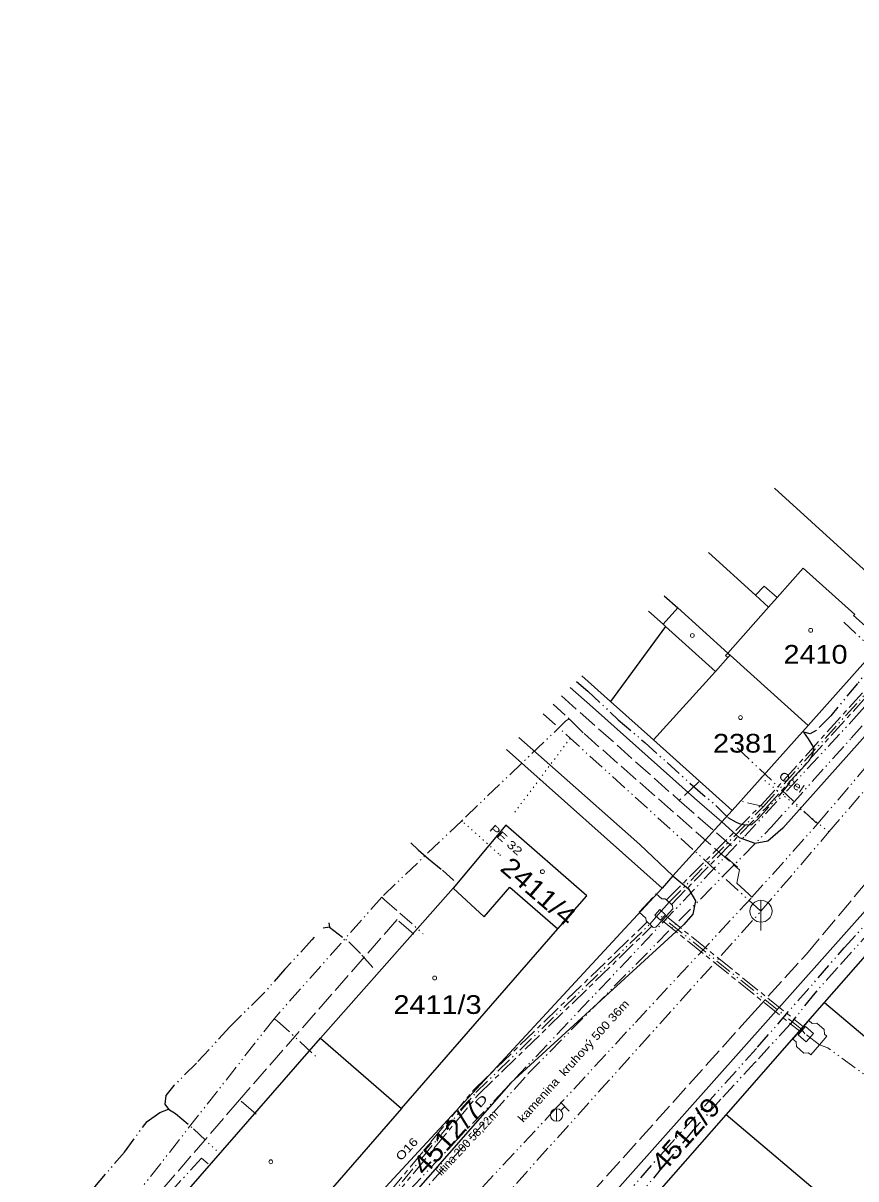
# Model space of a CAD drawing. Extents: x -683947 to -683762, y -1065756 to -1065543.
# Drawn here: x -683919.6 to -683844, y -1065654 to -1065549.1 of the extents above; entities that cross this region are included whole.
import ezdxf

# ---------------------------------------------------------------- set-up
doc = ezdxf.new("R2010")
doc.units = 0
doc.header["$LTSCALE"] = 0.3
for name, pattern in [('DASH_DOUBLE_DOT', [9.2, 5, -1.2, 0.3, -1.2, 0.3, -1.2]), ('DOTTED', [1.5, 0.3, -1.2]), ('LONG_DASH_SHORT_DASH', [9.9, 6, -1.2, 1.5, -1.2]), ('LONG_DASHED', [7.5, 6, -1.5])]:
    doc.linetypes.add(name, pattern=pattern)
for name, color, linetype, lineweight in [('1', 7, 'Continuous', 25), ('10', 7, 'Continuous', 13), ('26', 7, 'LONG_DASH_SHORT_DASH', 13), ('30', 7, 'LONG_DASHED', 13), ('31', 7, 'DASH_DOUBLE_DOT', 13), ('35', 7, 'LONG_DASHED', 13), ('36', 7, 'DASH_DOUBLE_DOT', 25), ('4', 7, 'Continuous', 13), ('41', 7, 'DASH_DOUBLE_DOT', 13), ('46', 7, 'DASH_DOUBLE_DOT', 13), ('5', 7, 'Continuous', 13), ('50', 7, 'LONG_DASHED', 13), ('51', 7, 'DOTTED', 13)]:
    doc.layers.add(name, color=color, linetype=linetype, lineweight=lineweight)
for name, color, linetype in [('15', 7, 'Continuous'), ('16', 7, 'Continuous'), ('19', 7, 'Continuous'), ('2', 7, 'Continuous')]:
    doc.layers.add(name, color=color, linetype=linetype)

msp = doc.modelspace()

# ---------------------------------------------------------------- linework, layer by layer
at = {"layer": '1'}
for p, q in [((-683799.39, -1065564.75), (-683850.61, -1065622.17)), ((-683844.35, -1065631.04), (-683799.69, -1065580.85)), ((-683839.12, -1065602.44), (-683851.364, -1065591.312)), ((-683861.375, -1065601.074), (-683860.14, -1065602.18)), ((-683862.798, -1065602.462), (-683861.47, -1065603.66)), ((-683860.14, -1065602.18), (-683855.6, -1065606.27)), ((-683861.25, -1065603.86), (-683866.24, -1065610.67)), ((-683861.47, -1065603.66), (-683861.25, -1065603.86)), ((-683841.53, -1065605.24), (-683848.31, -1065612.84)), ((-683855.6, -1065606.27), (-683855.38, -1065606.47)), ((-683855.38, -1065606.47), (-683848.31, -1065612.84)), ((-683868.839, -1065608.352), (-683866.24, -1065610.67)), ((-683866.24, -1065610.67), (-683862.34, -1065614.14)), ((-683848.31, -1065612.84), (-683855.19, -1065620.55)), ((-683862.34, -1065614.14), (-683855.19, -1065620.55)), ((-683861.55, -1065627.6), (-683875.681, -1065615.023)), ((-683855.19, -1065620.55), (-683856.15, -1065621.6)), ((-683875.75, -1065621.9), (-683880.52, -1065627.61)), ((-683868.4, -1065628.3), (-683875.75, -1065621.9)), ((-683856.15, -1065621.6), (-683860.6, -1065626.48)), ((-683854.54, -1065623.06), (-683856.15, -1065621.6)), ((-683860.6, -1065626.48), (-683861.55, -1065627.6)), ((-683860.6, -1065626.48), (-683859.17, -1065627.69)), ((-683861.55, -1065627.6), (-683902.49, -1065671.82)), ((-683880.52, -1065627.61), (-683892.56, -1065641.22)), ((-683880.52, -1065627.61), (-683877.73, -1065630.22)), ((-683877.73, -1065630.22), (-683875.38, -1065627.52)), ((-683875.38, -1065627.52), (-683871.02, -1065631.31)), ((-683859.17, -1065627.69), (-683858.54, -1065628.75)), ((-683871.02, -1065631.31), (-683868.4, -1065628.3)), ((-683858.54, -1065628.75), (-683858.77, -1065629.96)), ((-683858.77, -1065629.96), (-683859.58, -1065630.9)), ((-683885.21, -1065647.62), (-683871.02, -1065631.31)), ((-683867.65, -1065657.22), (-683844.35, -1065631.04)), ((-683846.81, -1065638), (-683842.21, -1065632.76)), ((-683855.75, -1065648.18), (-683846.81, -1065638)), ((-683846.81, -1065638), (-683835.924, -1065647.198)), ((-683909.31, -1065660.38), (-683892.56, -1065641.22)), ((-683863.13, -1065656.59), (-683855.75, -1065648.18)), ((-683845.419, -1065656.92), (-683855.75, -1065648.18))]:
    msp.add_line(p, q, dxfattribs=at)
for points in [[(-683850.61, -1065622.17), (-683851.95, -1065623.34), (-683853.1, -1065623.57), (-683854.54, -1065623.06)], [(-683859.58, -1065630.9), (-683875.3, -1065645.28), (-683888.43, -1065660.25), (-683897.91, -1065674.98), (-683898.51, -1065675.59)], [(-683892.56, -1065641.22), (-683885.21, -1065647.62), (-683901.98, -1065666.88)]]:
    msp.add_lwpolyline(points, dxfattribs=at)
at = {"layer": '10'}
for p, q in [((-683852.585, -1065628.702), (-683852.585, -1065631.45)), ((-683870.777, -1065647.051), (-683869.986, -1065647.842)), ((-683871.138, -1065648.762), (-683871.137, -1065647.644)), ((-683870.743, -1065647.808), (-683870.381, -1065647.446))]:
    msp.add_line(p, q, dxfattribs=at)
for centre, radius in [((-683852.585, -1065629.704), 1), ((-683871.138, -1065648.203), 0.559)]:
    msp.add_circle(centre, radius, dxfattribs=at)
at = {"layer": '26'}
for p, q in [((-683861.2, -1065630.15), (-683848.73, -1065640.2)), ((-683861.56, -1065630.54), (-683849.07, -1065640.6))]:
    msp.add_line(p, q, dxfattribs=at)
for points in [[(-683861.16, -1065628.68), (-683852.54, -1065620.04), (-683840.5, -1065606.72), (-683835.07, -1065600.93)], [(-683860.72, -1065629.09), (-683852.18, -1065620.38), (-683840.14, -1065607.06), (-683834.72, -1065601.23)], [(-683903.43, -1065669.5), (-683897.38, -1065669.58), (-683878.26, -1065646.37), (-683862.48, -1065631.07)], [(-683903.42, -1065669.04), (-683897.66, -1065668.98), (-683878.7, -1065645.97), (-683862.91, -1065630.67)]]:
    msp.add_lwpolyline(points, dxfattribs=at)
for points in [[(-683863.63, -1065629.78), (-683862.1, -1065628.12), (-683861.58, -1065628.59), (-683861.27, -1065628.58), (-683861.16, -1065628.68), (-683860.72, -1065629.09), (-683860.61, -1065629.19), (-683860.6, -1065629.5), (-683861.2, -1065630.15), (-683861.56, -1065630.54), (-683862.13, -1065631.16), (-683862.37, -1065631.17), (-683862.48, -1065631.07), (-683862.91, -1065630.67), (-683863.02, -1065630.57), (-683863.03, -1065630.33)], [(-683862.23, -1065630.06), (-683861.76, -1065629.55), (-683861.24, -1065630.02), (-683861.72, -1065630.53)], [(-683849.7, -1065641.32), (-683849.07, -1065640.6), (-683848.73, -1065640.2), (-683848.24, -1065639.64), (-683847.95, -1065639.9), (-683847.53, -1065639.86), (-683846.85, -1065640.45), (-683846.81, -1065640.88), (-683846.6, -1065641.06), (-683847.26, -1065641.82), (-683847.66, -1065642.29), (-683848.05, -1065642.74), (-683848.27, -1065642.56), (-683848.69, -1065642.59), (-683849.37, -1065642), (-683849.4, -1065641.57)], [(-683849.2, -1065640.93), (-683848.55, -1065640.17), (-683847.82, -1065640.8), (-683848.47, -1065641.56)]]:
    msp.add_lwpolyline(points, close=True, dxfattribs=at)
at = {"layer": '30', "linetype": 'DASH_DOUBLE_DOT'}
msp.add_line((-683852.36, -1065620.21), (-683854.49, -1065619.69), dxfattribs=at)
at = {"layer": '31'}
for p, q in [((-683852.36, -1065620.21), (-683840.32, -1065606.89)), ((-683854.06, -1065622.89), (-683844.16, -1065612.25))]:
    msp.add_line(p, q, dxfattribs=at)
for points in [[(-683844.16, -1065612.25), (-683839.52, -1065607), (-683832.27, -1065598.52), (-683799.27, -1065561.98), (-683793.42, -1065555.08), (-683787.795, -1065549.096)], [(-683851.65, -1065622.08), (-683844.4, -1065614), (-683839.42, -1065608.5)], [(-683861.88, -1065629.98), (-683860.92, -1065628.89), (-683852.36, -1065620.21)], [(-683914.84, -1065689.19), (-683909.62, -1065682.86), (-683896.8, -1065669.54), (-683888.32, -1065659.06), (-683854.06, -1065622.89)], [(-683906.37, -1065683.43), (-683899.08, -1065675.36), (-683887.96, -1065660.41), (-683873.71, -1065644.44), (-683851.65, -1065622.08)], [(-683904.31, -1065669.83), (-683903.47, -1065669.28), (-683897.52, -1065669.28), (-683878.48, -1065646.17), (-683862.67, -1065630.88), (-683861.88, -1065629.98)], [(-683847.26, -1065641.82), (-683848.59, -1065640.84), (-683848.91, -1065640.4), (-683861.88, -1065629.98)], [(-683837.249, -1065648.554), (-683837.47, -1065648.39), (-683839.53, -1065647.2), (-683846.53, -1065642.1), (-683847.26, -1065641.82)], [(-683902.77, -1065652.64), (-683903.37, -1065652.11), (-683910.28, -1065659.68), (-683910.65, -1065661.62), (-683904.7, -1065669)]]:
    msp.add_lwpolyline(points, dxfattribs=at)
at = {"layer": '35'}
msp.add_line((-683853.691, -1065628.152), (-683853.405, -1065628.437), dxfattribs=at)
for points in [[(-683896.24, -1065687.55), (-683894.71, -1065685.72), (-683893.48, -1065684.13), (-683891.61, -1065681.955), (-683887.89, -1065677.63), (-683886.16, -1065675.53), (-683853.44, -1065639.1), (-683848.45, -1065633.59), (-683843.114, -1065627.22), (-683843.08, -1065627.18), (-683831.4, -1065614.21), (-683820.06, -1065601.41), (-683812.91, -1065593.55), (-683807.75, -1065587.62), (-683793.84, -1065572.21), (-683791.969, -1065570.179), (-683790.708, -1065568.809), (-683790.074, -1065568.129)], [(-683870.696, -1065610.163), (-683860.01, -1065619.65), (-683855.11, -1065623.91)], [(-683870.005, -1065612.249), (-683868.647, -1065613.585), (-683854.756, -1065625.769), (-683854.545, -1065625.954), (-683854.783, -1065627.15), (-683853.691, -1065628.152)], [(-683899.923, -1065646.829), (-683919.379, -1065669.399), (-683919.57, -1065669.63)]]:
    msp.add_lwpolyline(points, dxfattribs=at)
at = {"layer": '36', "lineweight": 13}
for p, q in [((-683871.452, -1065610.9), (-683870.005, -1065612.249)), ((-683870.287, -1065612.435), (-683870.005, -1065612.249)), ((-683854.71, -1065625.713), (-683856.125, -1065624.479))]:
    msp.add_line(p, q, dxfattribs=at)
for points in [[(-683853.405, -1065628.437), (-683847.424, -1065621.75), (-683837.692, -1065610.319), (-683826.563, -1065598.101), (-683821.765, -1065592.734), (-683810.241, -1065579.722), (-683798.152, -1065565.762), (-683797.335, -1065564.872), (-683796.84, -1065564.29)], [(-683870.287, -1065612.435), (-683879.753, -1065621.49), (-683887.014, -1065628.435), (-683896.789, -1065639.476), (-683918.858, -1065667.62)], [(-683893.079, -1065671.05), (-683871.468, -1065647.886), (-683863.976, -1065639.798), (-683853.405, -1065628.437)]]:
    msp.add_lwpolyline(points, dxfattribs=at)
at = {"layer": '36'}
for points in [[(-683842.215, -1065607.115), (-683843.83, -1065609.03), (-683846.24, -1065611.96), (-683847.58, -1065613.3), (-683848.12, -1065613.6), (-683848.69, -1065613.45)], [(-683869.343, -1065608.844), (-683868.3, -1065609.72), (-683865.54, -1065612.33), (-683863.14, -1065614.38), (-683861.11, -1065616.21), (-683858.79, -1065618.31), (-683856.69, -1065620.11), (-683855.58, -1065621.21), (-683854.85, -1065621.62), (-683854.57, -1065621.75), (-683854.07, -1065621.88), (-683853.43, -1065621.83), (-683852.88, -1065621.35), (-683850.88, -1065619.18), (-683849.15, -1065617.08), (-683848.11, -1065615.9), (-683847.84, -1065615.36), (-683847.8, -1065614.86), (-683848.27, -1065614.07), (-683848.69, -1065613.45)], [(-683884.364, -1065623.49), (-683883.71, -1065624.12), (-683882.78, -1065624.95), (-683881.51, -1065625.99), (-683880.48, -1065626.93)], [(-683891.81, -1065630.751), (-683891.76, -1065631.15), (-683892.33, -1065631.258)], [(-683891.76, -1065631.15), (-683890.01, -1065632.48), (-683888.81, -1065633.69), (-683887.63, -1065635.07)], [(-683842.53, -1065631.36), (-683845.66, -1065634.87), (-683847.69, -1065637.13), (-683849.92, -1065639.94), (-683853.13, -1065643.44), (-683856.24, -1065646.78), (-683858.76, -1065649.61), (-683861.4, -1065652.77), (-683863.72, -1065655.58)], [(-683893.15, -1065632.058), (-683893.35, -1065632.31), (-683895.8, -1065634.96), (-683897.77, -1065637.2), (-683900.81, -1065640.2), (-683903.84, -1065643.51), (-683905.89, -1065645.54), (-683906.62, -1065646.43), (-683906.71, -1065647.21), (-683906.37, -1065647.66)], [(-683918.74, -1065659.99), (-683918.38, -1065659.72), (-683916.63, -1065658.62), (-683914.98, -1065657.12), (-683913.07, -1065654.72), (-683910.37, -1065651.57), (-683908.32, -1065648.79), (-683907.17, -1065647.97), (-683906.37, -1065647.66)], [(-683906.37, -1065647.66), (-683905.73, -1065648.06), (-683904.1, -1065649.47), (-683902.01, -1065651.44)]]:
    msp.add_lwpolyline(points, dxfattribs=at)
at = {"layer": '4'}
for p, q in [((-683853.09, -1065601.01), (-683857.361, -1065597.16)), ((-683848.77, -1065598.58), (-683851.11, -1065601.23)), ((-683844.07, -1065602.76), (-683848.77, -1065598.58)), ((-683852.3, -1065600.21), (-683853.09, -1065601.01)), ((-683851.11, -1065601.23), (-683852.3, -1065600.21)), ((-683861.47, -1065603.66), (-683860.14, -1065602.18)), ((-683855.6, -1065606.27), (-683851.89, -1065602.1)), ((-683861.25, -1065603.86), (-683856.72, -1065607.95)), ((-683855.58, -1065606.69), (-683856.72, -1065607.95)), ((-683856.72, -1065607.95), (-683862.34, -1065614.14)), ((-683869.905, -1065609.392), (-683867.87, -1065611.2)), ((-683867.87, -1065611.2), (-683858.62, -1065619.44)), ((-683871.24, -1065616.88), (-683874.581, -1065613.951)), ((-683858.62, -1065619.44), (-683856.15, -1065621.6))]:
    msp.add_line(p, q, dxfattribs=at)
for points in [[(-683853.09, -1065601.01), (-683851.89, -1065602.1), (-683851.11, -1065601.23)], [(-683841.53, -1065605.24), (-683844.18, -1065602.88), (-683844.07, -1065602.76)], [(-683855.38, -1065606.47), (-683855.58, -1065606.69), (-683855.8, -1065606.49), (-683855.6, -1065606.27)], [(-683860.6, -1065626.48), (-683863.57, -1065623.65), (-683871.24, -1065616.88)]]:
    msp.add_lwpolyline(points, dxfattribs=at)
at = {"layer": '41', "lineweight": 25}
msp.add_lwpolyline([(-683907.26, -1065705.67), (-683893.37, -1065687.98), (-683887.71, -1065681.96), (-683876.81, -1065669.67), (-683869.01, -1065660.17), (-683861.43, -1065651.54), (-683852.89, -1065642.04), (-683845.02, -1065633.03), (-683836.31, -1065623.45), (-683820.34, -1065605.7), (-683789.54, -1065571.05), (-683781.76, -1065562.31), (-683777.124, -1065557.504)], dxfattribs=at)
at = {"layer": '46'}
for p, q in [((-683872.355, -1065611.781), (-683869.903, -1065614.004)), ((-683852.585, -1065629.704), (-683869.903, -1065614.004)), ((-683876.643, -1065656.48), (-683852.585, -1065629.704))]:
    msp.add_line(p, q, dxfattribs=at)
msp.add_lwpolyline([(-683852.585, -1065629.704), (-683846.423, -1065622.515), (-683835.949, -1065610.295), (-683830.355, -1065603.769), (-683826.197, -1065598.918)], dxfattribs=at)
at = {"layer": '5'}
for centre in [(-683848.077, -1065604.209), (-683858.817, -1065604.679), (-683854.447, -1065612.129), (-683872.427, -1065626.119), (-683882.207, -1065635.769), (-683897.077, -1065652.449)]:
    msp.add_circle(centre, 0.175, dxfattribs=at)
at = {"layer": '50'}
for p, q in [((-683858.22, -1065617.95), (-683860.01, -1065619.65)), ((-683898.413, -1065648.141), (-683899.923, -1065646.829))]:
    msp.add_line(p, q, dxfattribs=at)
msp.add_lwpolyline([(-683884.103, -1065631.779), (-683885.613, -1065630.467), (-683899.923, -1065646.829)], dxfattribs=at)
at = {"layer": '51'}
for p, q in [((-683869.903, -1065614.004), (-683875.123, -1065620.97)), ((-683846.423, -1065622.515), (-683852.885, -1065617.332))]:
    msp.add_line(p, q, dxfattribs=at)
at = {"layer": '51', "linetype": 'DASH_DOUBLE_DOT'}
for points in [[(-683837.692, -1065610.319), (-683837.85, -1065610.18), (-683845.274, -1065603.286)], [(-683847.424, -1065621.75), (-683847.6, -1065621.64), (-683854.966, -1065614.685)], [(-683887.014, -1065628.435), (-683886.775, -1065628.66), (-683885.383, -1065629.871), (-683883.259, -1065631.756)], [(-683896.789, -1065639.476), (-683896.496, -1065639.644), (-683892.926, -1065642.949)]]:
    msp.add_lwpolyline(points, dxfattribs=at)
at = {"layer": '51'}
msp.add_lwpolyline([(-683879.753, -1065621.49), (-683879.55, -1065621.672), (-683876.308, -1065624.578), (-683876.15, -1065624.719)], dxfattribs=at)

# ---------------------------------------------------------------- texts
at = {"layer": '15'}
for s, width, p in [('kamenina  kruhový 500 36m', 1.15, (-683874.172, -1065648.942)), ('D', 1.6, (-683878.098, -1065647.626))]:
    msp.add_text(s, height=0.75, rotation=48.06, dxfattribs=dict(at, width=width)).set_placement(p)
at = {"layer": '16'}
msp.add_text('litina 200 58,22m', height=0.75, rotation=46.99, dxfattribs=at).set_placement((-683881.603, -1065653.764))
at = {"layer": '16', "width": 1.25}
msp.add_text('O16', height=0.75, rotation=46.99, dxfattribs=at).set_placement((-683885.269, -1065652.418))
at = {"layer": '19'}
for s, rotation, width, p in [('Ocel ', 325.39, 1.2, (-683851.034, -1065617.594)), ('PE 32', 318.133, 1.3, (-683877.304, -1065622.342))]:
    msp.add_text(s, height=0.75, rotation=rotation, dxfattribs=dict(at, width=width)).set_placement(p)
at = {"layer": '2', "width": 1.15}
for s, p in [('2410', (-683850.54, -1065607.24)), ('2381', (-683856.94, -1065615.31)), ('2411/3', (-683885.95, -1065639.03))]:
    msp.add_text(s, height=1.7, dxfattribs=at).set_placement(p)
for s, rotation, p in [('2411/4', 319.273, (-683876.37, -1065625.94)), ('4512/7', 48.013, (-683883.12, -1065653.79)), ('4512/9', 48.396, (-683861.44, -1065653.54))]:
    msp.add_text(s, height=1.7, rotation=rotation, dxfattribs=at).set_placement(p)

doc.saveas('drawing.dxf')
